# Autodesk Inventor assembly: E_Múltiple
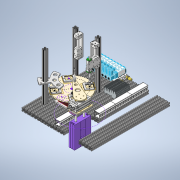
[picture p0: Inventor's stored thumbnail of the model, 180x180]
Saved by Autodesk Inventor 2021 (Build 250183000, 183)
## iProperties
Created: 2021-02
Part Number: E_Múltiple
Document SubType Name: Assembly
Designer: ATOUZA
Author: ATOUZA
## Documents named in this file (22)
- D:\01 Paralaia\Grupos de Traballo\GT Maquetas\CAD 3D\E_Múltiple\E_Múltiple.iam
- D:\01 Paralaia\Grupos de Traballo\GT Maquetas\CAD 3D\E_Múltiple\SMC_JP_MSQXB10AM9B0\MSQXB10A-M9B(0).iam
- D:\01 Paralaia\Grupos de Traballo\GT Maquetas\CAD 3D\E_Múltiple\Perfil 20x20 B R6.ipt
- D:\01 Paralaia\Grupos de Traballo\GT Maquetas\CAD 3D\E_Múltiple\CilindroElevador\CilindroElevador.iam
- D:\01 Paralaia\Grupos de Traballo\GT Maquetas\CAD 3D\E_Múltiple\Perfil 20x20 B R6-Corto.ipt
- D:\01 Paralaia\Grupos de Traballo\GT Maquetas\CAD 3D\E_Múltiple\Placa cilindro rotatorio.ipt
- D:\01 Paralaia\Grupos de Traballo\GT Maquetas\CAD 3D\E_Múltiple\Placa cilindro elevador.ipt
- D:\01 Paralaia\Grupos de Traballo\GT Maquetas\CAD 3D\E_Múltiple\Brazo cilindro rotatorio.ipt
- D:\01 Paralaia\Grupos de Traballo\GT Maquetas\CAD 3D\E_Múltiple\ZPT32SCK30\ZPT32CSK30-04-A10_(S) Silicon rubber.iam
- D:\01 Paralaia\Grupos de Traballo\GT Maquetas\CAD 3D\E_Múltiple\CY3R10-50-M9B\CY3R10-50-M9B(0_0_0).iam
- D:\01 Paralaia\Grupos de Traballo\GT Maquetas\CAD 3D\E_Múltiple\Perfil 20x20 B R6 Columna.ipt
- D:\01 Paralaia\Grupos de Traballo\GT Maquetas\CAD 3D\E_Múltiple\ResistenciaKTR\Resistencia KTR.iam
- D:\01 Paralaia\Grupos de Traballo\GT Maquetas\CAD 3D\E_Múltiple\Cubo.ipt
- D:\01 Paralaia\Grupos de Traballo\GT Maquetas\CAD 3D\E_Múltiple\PlacaUnionKTR.ipt
- D:\01 Paralaia\Grupos de Traballo\GT Maquetas\CAD 3D\E_Múltiple\Electroválvulas\BloqueElectroválvulas.iam
- D:\01 Paralaia\Grupos de Traballo\GT Maquetas\CAD 3D\E_Múltiple\Borne para detectoresactuadores - PTIO 1,5-S-3 - 3244410\pxc_3244410_02_PTIO-1-5-S-3_3D.ipt
- D:\01 Paralaia\Grupos de Traballo\GT Maquetas\CAD 3D\E_Múltiple\Canaleta 30x30\7308-1.iam
- D:\01 Paralaia\Grupos de Traballo\GT Maquetas\CAD 3D\E_Múltiple\Colibri.ipt
- D:\01 Paralaia\Grupos de Traballo\GT Maquetas\CAD 3D\E_Múltiple\Plato Colibri.ipt
- D:\01 Paralaia\Grupos de Traballo\GT Maquetas\CAD 3D\E_Múltiple\Base Colibri.ipt
- D:\01 Paralaia\Grupos de Traballo\GT Maquetas\CAD 3D\E_Múltiple\Soporte sensores.ipt
- D:\01 Paralaia\Grupos de Traballo\GT Maquetas\CAD 3D\E_Múltiple\SoportePiezasPlato.ipt
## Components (70 placed, 20 different names)
1. MSQXB10A-M9B(0):1 [sub-assembly] — Ángulo:3, Insertar:1, Insertar:2, Nivelación:9, Coincidencia:6, Ángulo:4
2. CilindroElevador:1 [sub-assembly] — Ángulo:2, Coincidencia:3, Nivelación:2, Nivelación:4, Insertar:6, Nivelación:8
3. Placa cilindro rotatorio:1 — Insertar:1, Insertar:2, Insertar:3, Insertar:5
4. Placa cilindro elevador:1 — Insertar:3, Insertar:5, Insertar:6, Nivelación:8
5. Brazo cilindro rotatorio:1 — Nivelación:9, Coincidencia:6, Ángulo:4, Insertar:7
6. ZPT32CSK30-04-A10_(S) Silicon rubber:1 [sub-assembly] — Insertar:7
7. Cubo:1 — Coincidencia:36
8. BloqueElectroválvulas:1 [sub-assembly] — Coincidencia:17, Nivelación:23
9. 7308-1:3 [sub-assembly] — Coincidencia:21
10. Soporte sensores:1 — Nivelación:28
11. Perfil 20x20 B R6 480:23 — Coincidencia:29, Nivelación:29, Nivelación:30
12. SoportePiezasPlato:2 — Coincidencia:32, Coincidencia:33
13. SoportePiezasPlato:3 — Coincidencia:34, Coincidencia:35, Coincidencia:36
14. SoportePiezasPlato:4 — Coincidencia:37, Coincidencia:38
15. Resistencia KTR:1 [sub-assembly] — Coincidencia:13, Nivelación:15, Nivelación:22, Coincidencia:26
16. PlacaUnionKTR:1 — Insertar:12, Insertar:13, Coincidencia:13, Nivelación:15, Nivelación:22
17. Perfil 20x20 B R6 480:21 — Coincidencia:8, Nivelación:13, Coincidencia:11, Ángulo:5, Nivelación:24
18. CY3R10-50-M9B(0_0_0):1 [sub-assembly] — Nivelación:13, Coincidencia:11, Coincidencia:12, Insertar:12, Insertar:13
19. Colibri:1 — Coincidencia:24, Coincidencia:25
20. Plato Colibri:1 — Coincidencia:25, Coincidencia:26, Nivelación:28, Coincidencia:30, Coincidencia:31, Coincidencia:32, Coincidencia:33, Coincidencia:34, Coincidencia:35, Coincidencia:37, Coincidencia:38
21. Base Colibri:1 — Coincidencia:23, Coincidencia:24
22. SoportePiezasPlato:1 — Coincidencia:30, Coincidencia:31
23. CY3R10-50-M9B(0_0_0):2 [sub-assembly] — Coincidencia:28, Ángulo:7, Nivelación:26
24. Perfil 20x20 B R6 480:22 — Coincidencia:27, Coincidencia:28, Ángulo:7, Nivelación:26, Nivelación:27
25. Perfil 20x20 B R6 480:1 — Nivelación:1, Coincidencia:3, Nivelación:2, Coincidencia:4, Nivelación:6, Nivelación:7, Coincidencia:5, Coincidencia:8
26. Perfil 20x20 B R6 480:2
27. Perfil 20x20 B R6 480:3 — Coincidencia:12
28. Perfil 20x20 B R6 480:4
29. Perfil 20x20 B R6 480:5
30. Perfil 20x20 B R6 480:6 — Nivelación:4
31. Perfil 20x20 B R6 480:7
32. Perfil 20x20 B R6 480:8 — Coincidencia:18, Coincidencia:23
33. Perfil 20x20 B R6 480:9 — Nivelación:23
34. Perfil 20x20 B R6 480:10
35. Perfil 20x20 B R6 480:11 — Coincidencia:17, Coincidencia:22, Nivelación:30
36. Perfil 20x20 B R6 480:12 — Coincidencia:21, Coincidencia:27, Coincidencia:29
37. Perfil 20x20 B R6 480:13 — Coincidencia:19, Nivelación:27, Nivelación:29
38. Perfil 20x20 B R6 480:15
39. Perfil 20x20 B R6 480:16
40. Perfil 20x20 B R6 480:17 — Nivelación:6
41. Perfil 20x20 B R6 480:18 — Nivelación:5, Coincidencia:4
42. Perfil 20x20 B R6 480:19 — Coincidencia:5
43. Perfil 20x20 B R6 480:20 — Nivelación:7, Ángulo:5, Nivelación:24
44. pxc_3244410_02_PTIO-1-5-S-3_3D:2 — Coincidencia:19
45. pxc_3244410_02_PTIO-1-5-S-3_3D:3
46. pxc_3244410_02_PTIO-1-5-S-3_3D:4
47. pxc_3244410_02_PTIO-1-5-S-3_3D:5
48. pxc_3244410_02_PTIO-1-5-S-3_3D:6
49. pxc_3244410_02_PTIO-1-5-S-3_3D:7
50. pxc_3244410_02_PTIO-1-5-S-3_3D:8
51. pxc_3244410_02_PTIO-1-5-S-3_3D:9
52. pxc_3244410_02_PTIO-1-5-S-3_3D:10
53. pxc_3244410_02_PTIO-1-5-S-3_3D:11
54. pxc_3244410_02_PTIO-1-5-S-3_3D:12
55. pxc_3244410_02_PTIO-1-5-S-3_3D:13
56. pxc_3244410_02_PTIO-1-5-S-3_3D:14
57. pxc_3244410_02_PTIO-1-5-S-3_3D:15
58. pxc_3244410_02_PTIO-1-5-S-3_3D:16
59. pxc_3244410_02_PTIO-1-5-S-3_3D:17
60. pxc_3244410_02_PTIO-1-5-S-3_3D:18
61. pxc_3244410_02_PTIO-1-5-S-3_3D:19
62. pxc_3244410_02_PTIO-1-5-S-3_3D:20
63. pxc_3244410_02_PTIO-1-5-S-3_3D:21
64. pxc_3244410_02_PTIO-1-5-S-3_3D:22
65. pxc_3244410_02_PTIO-1-5-S-3_3D:23
66. pxc_3244410_02_PTIO-1-5-S-3_3D:24
67. pxc_3244410_02_PTIO-1-5-S-3_3D:25
68. Canaleta [sub-assembly] — Coincidencia:18
69. 7308-1:2 [sub-assembly] — Coincidencia:22
70. 7308-1:4 [sub-assembly]
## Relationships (60: Mate 29, Flush 18, Insert 8, Angle 5)
- Nivelación:1 [Flush]: Perfil 20x20 B R6 480:1
- Ángulo:2 [Angle]: CilindroElevador:1
- Coincidencia:3 [Mate]: CilindroElevador:1 ↔ Perfil 20x20 B R6 480:1
- Nivelación:2 [Flush]: CilindroElevador:1 ↔ Perfil 20x20 B R6 480:1
- Nivelación:4 [Flush]: CilindroElevador:1 ↔ Perfil 20x20 B R6 480:6
- Nivelación:5 [Flush]: Perfil 20x20 B R6 480:18
- Coincidencia:4 [Mate]: Perfil 20x20 B R6 480:1 ↔ Perfil 20x20 B R6 480:18
- Nivelación:6 [Flush]: Perfil 20x20 B R6 480:1 ↔ Perfil 20x20 B R6 480:17
- Nivelación:7 [Flush]: Perfil 20x20 B R6 480:1 ↔ Perfil 20x20 B R6 480:20
- Coincidencia:5 [Mate]: Perfil 20x20 B R6 480:1 ↔ Perfil 20x20 B R6 480:19
- Ángulo:3 [Angle]: MSQXB10A-M9B(0):1
- Insertar:1: MSQXB10A-M9B(0):1 ↔ Placa cilindro rotatorio:1
- Insertar:2: MSQXB10A-M9B(0):1 ↔ Placa cilindro rotatorio:1
- Insertar:3: Placa cilindro rotatorio:1 ↔ Placa cilindro elevador:1
- Insertar:5: Placa cilindro rotatorio:1 ↔ Placa cilindro elevador:1
- Insertar:6: CilindroElevador:1 ↔ Placa cilindro elevador:1
- Nivelación:8 [Flush]: CilindroElevador:1 ↔ Placa cilindro elevador:1
- Nivelación:9 [Flush]: MSQXB10A-M9B(0):1 ↔ Brazo cilindro rotatorio:1
- Coincidencia:6 [Mate]: MSQXB10A-M9B(0):1 ↔ Brazo cilindro rotatorio:1
- Ángulo:4 [Angle]: MSQXB10A-M9B(0):1 ↔ Brazo cilindro rotatorio:1
- Insertar:7: Brazo cilindro rotatorio:1 ↔ ZPT32CSK30-04-A10_(S) Silicon rubber:1
- Coincidencia:8 [Mate]: Perfil 20x20 B R6 480:21 ↔ Perfil 20x20 B R6 480:1
- Nivelación:13 [Flush]: Perfil 20x20 B R6 480:21 ↔ CY3R10-50-M9B(0_0_0):1
- Coincidencia:11 [Mate]: Perfil 20x20 B R6 480:21 ↔ CY3R10-50-M9B(0_0_0):1
- Coincidencia:12 [Mate]: CY3R10-50-M9B(0_0_0):1 ↔ Perfil 20x20 B R6 480:3
- Insertar:12: PlacaUnionKTR:1 ↔ CY3R10-50-M9B(0_0_0):1
- Insertar:13: PlacaUnionKTR:1 ↔ CY3R10-50-M9B(0_0_0):1
- Coincidencia:13 [Mate]: Resistencia KTR:1 ↔ PlacaUnionKTR:1
- Nivelación:15 [Flush]: Resistencia KTR:1 ↔ PlacaUnionKTR:1
- Coincidencia:17 [Mate]: BloqueElectroválvulas:1 ↔ Perfil 20x20 B R6 480:11
- Coincidencia:18 [Mate]: Perfil 20x20 B R6 480:8 ↔ Canaleta
- Coincidencia:19 [Mate]: Perfil 20x20 B R6 480:13 ↔ pxc_3244410_02_PTIO-1-5-S-3_3D:2
- Nivelación:22 [Flush]: Resistencia KTR:1 ↔ PlacaUnionKTR:1
- Ángulo:5 [Angle]: Perfil 20x20 B R6 480:21 ↔ Perfil 20x20 B R6 480:20
- Coincidencia:21 [Mate]: 7308-1:3 ↔ Perfil 20x20 B R6 480:12
- Coincidencia:22 [Mate]: Perfil 20x20 B R6 480:11 ↔ 7308-1:2
- Coincidencia:23 [Mate]: Base Colibri:1 ↔ Perfil 20x20 B R6 480:8
- Coincidencia:24 [Mate]: Colibri:1 ↔ Base Colibri:1
- Coincidencia:25 [Mate]: Colibri:1 ↔ Plato Colibri:1
- Nivelación:23 [Flush]: BloqueElectroválvulas:1 ↔ Perfil 20x20 B R6 480:9
- Nivelación:24 [Flush]: Perfil 20x20 B R6 480:21 ↔ Perfil 20x20 B R6 480:20
- Coincidencia:26 [Mate]: Resistencia KTR:1 ↔ Plato Colibri:1
- Coincidencia:27 [Mate]: Perfil 20x20 B R6 480:22 ↔ Perfil 20x20 B R6 480:12
- Coincidencia:28 [Mate]: CY3R10-50-M9B(0_0_0):2 ↔ Perfil 20x20 B R6 480:22
- Ángulo:7 [Angle]: CY3R10-50-M9B(0_0_0):2 ↔ Perfil 20x20 B R6 480:22
- Nivelación:26 [Flush]: CY3R10-50-M9B(0_0_0):2 ↔ Perfil 20x20 B R6 480:22
- Nivelación:27 [Flush]: Perfil 20x20 B R6 480:22 ↔ Perfil 20x20 B R6 480:13
- Nivelación:28 [Flush]: Soporte sensores:1 ↔ Plato Colibri:1
- Coincidencia:29 [Mate]: Perfil 20x20 B R6 480:23 ↔ Perfil 20x20 B R6 480:12
- Nivelación:29 [Flush]: Perfil 20x20 B R6 480:23 ↔ Perfil 20x20 B R6 480:13
- Nivelación:30 [Flush]: Perfil 20x20 B R6 480:23 ↔ Perfil 20x20 B R6 480:11
- Coincidencia:30 [Mate]: Plato Colibri:1 ↔ SoportePiezasPlato:1
- Coincidencia:31 [Mate]: Plato Colibri:1 ↔ SoportePiezasPlato:1
- Coincidencia:32 [Mate]: SoportePiezasPlato:2 ↔ Plato Colibri:1
- Coincidencia:33 [Mate]: SoportePiezasPlato:2 ↔ Plato Colibri:1
- Coincidencia:34 [Mate]: SoportePiezasPlato:3 ↔ Plato Colibri:1
- Coincidencia:35 [Mate]: SoportePiezasPlato:3 ↔ Plato Colibri:1
- Coincidencia:36 [Mate]: Cubo:1 ↔ SoportePiezasPlato:3
- Coincidencia:37 [Mate]: SoportePiezasPlato:4 ↔ Plato Colibri:1
- Coincidencia:38 [Mate]: SoportePiezasPlato:4 ↔ Plato Colibri:1
